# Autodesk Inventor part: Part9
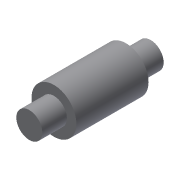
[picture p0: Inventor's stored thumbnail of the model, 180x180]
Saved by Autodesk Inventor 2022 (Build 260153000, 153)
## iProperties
Created: 2002-01
Part Number: Part9
Document SubType Name: Modeling
Designer: ***
Density: 1 g/cm^3
Material: Generic
Appearance: Default
Control State: 0
Master: False
Checked Out: False
Shininess: 77.0
Length Units: 11269
Angle Units: 11279
Time Units: 11290
Mass Units: 11283
Length Display Precision: 3
Angle Display Precision: 2
Density: 0.0
Volumn: 0.0
Area: 0.0
PropertySet Name: Model Information
Author: ***
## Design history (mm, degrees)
sketch "Sketch1"
  geometry: L1 (0.279, 23.245)-(5.19, 23.245); L2 (5.19, 23.245)-(5.19, 13.947); L3 (5.19, 13.947)-(8.761, 13.947); L4 (8.761, 13.947)-(8.761, -13.295); L5 (8.761, -13.295)-(5.19, -13.295); L6 (5.19, -13.295)-(5.19, -22.592); L7 (5.19, -22.592)-(0.279, -22.592); L8 (0.279, -22.592)-(0.279, 23.245)
  constraints: 16 end point, 5 parallel, 2 equal length, 1 collinear, 1 horizontal, 1 perpendicular
revolve "Revolution1" sketch "Sketch1" stored, may be unused: angle "d0" = 90 deg
body "Solid1"
